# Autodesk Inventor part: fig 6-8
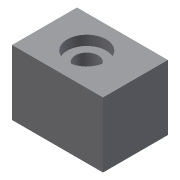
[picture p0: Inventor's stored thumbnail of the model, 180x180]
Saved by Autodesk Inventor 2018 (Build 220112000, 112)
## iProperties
Created: 2009-09
Part Number: fig 6-8
Document SubType Name: Modeling
Designer: Sham
Density: 1 g/cm^3
Material: Generic
Appearance: Default
Author: Sham
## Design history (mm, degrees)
sketch "Sketch1"
  geometry: L1 (-28, 20)-(0, 20); L2 (0, 20)-(0, 0); L3 (0, 0)-(-28, 0); L4 (-28, 0)-(-28, 20)
  constraints: 8 end point, 2 parallel, 1 horizontal, 1 perpendicular
extrude "Extrusion1" new body sketch "Sketch1" distance "d0" = 20; taper "d1" = 0 deg
hole "Hole1" diameter "d4" = 7; stored, may be unused: countersink angle "d8" = 90 deg, drill point angle "d10" = 118 deg; dims "d2" = 10, "d3" = 15, "d5" = 6, "d6" = 12, "d7" = 3, "d9" = 15
body "Solid1"
